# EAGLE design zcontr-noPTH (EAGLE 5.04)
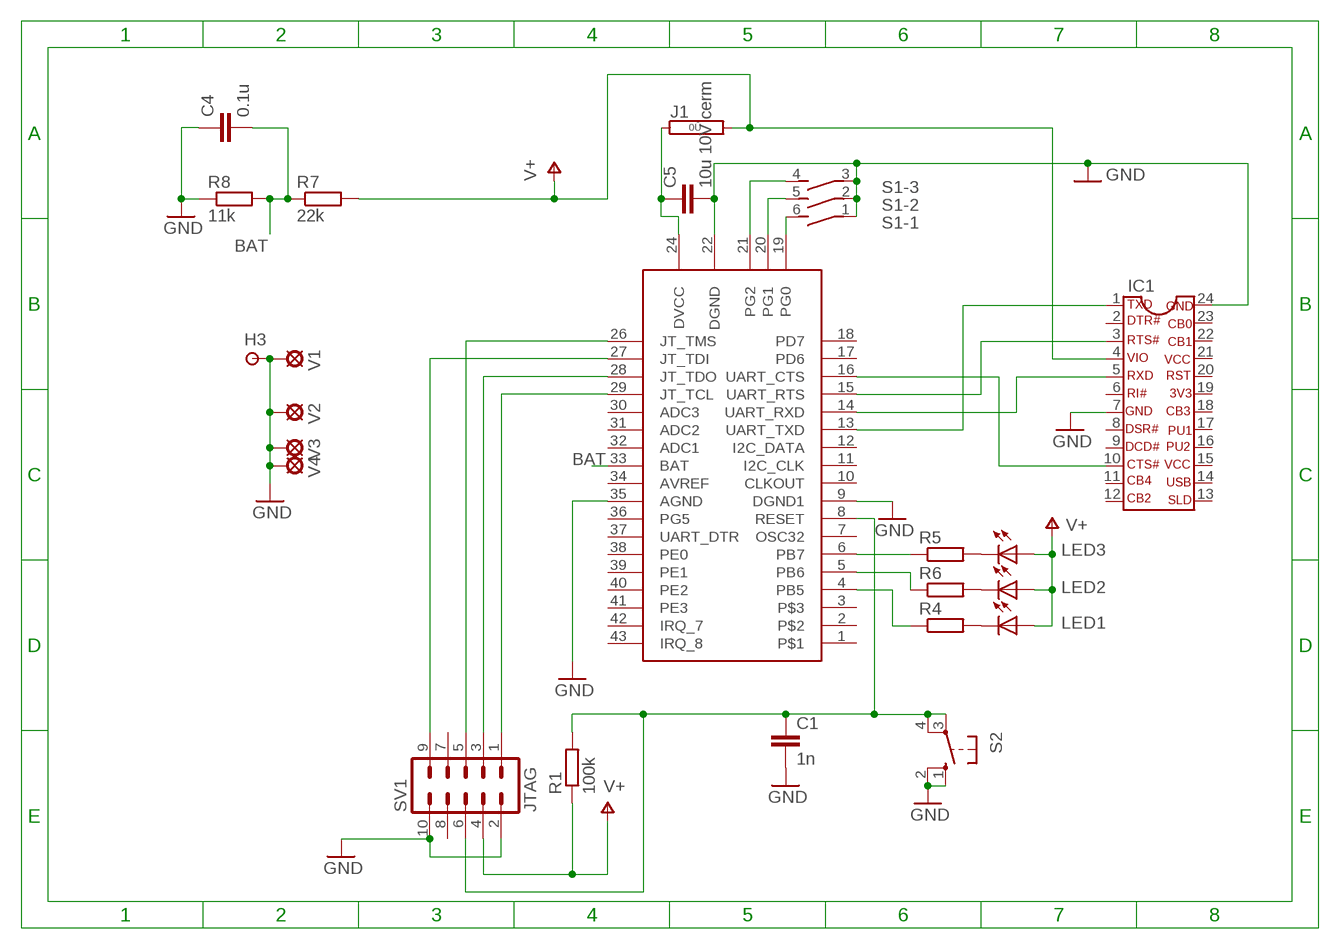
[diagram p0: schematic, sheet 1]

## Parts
C1  1n  C2.5P  [C025-030X050]
C4  0.1u  C5P  [C050-030-075]
C5  10u 10V cerm  CSMT0805  [C0805]
H3  HOLE/SMALL  [1,6/0,8]
IC1  UM232R-6  [DIL24-6]
J1  0R  [0R/10]
LED1  LED-3MM3MM  [HLMP-D105]
LED2  LED-3MM3MM  [HLMP-D105]
LED3  LED-3MM3MM  [HLMP-D105]
R1  100k  R  [0207/10]
R4  470  R  [0207/10]
R5  150  R  [0207/10]
R6  220  R  [0207/10]
R7  22k  R  [0207/10]
R8  11k  R  [0207/10]
S1  DIP-SW-03  [DIP-SW-3]
S2  10-XX  [B3F-10XX]
SV1  JTAG  ML10  [ML10]
U$1  ZDM-A1281-A2N  [ZIGSMD]
V1  HOLE/VIA  [LSP10]
V2  HOLE/VIA  [LSP10]
V3  HOLE/VIA  [LSP10]
V4  HOLE/VIA  [LSP10]

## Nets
BAT: C4.2 R7.1 R8.2 U$1.33(BAT)
GND [supply]: C1.2 C4.1 C5.2 H3.1(P) IC1.7 IC1.24 R8.1 S1.1 S1.2 S1.3 S2.1(S) S2.2(S1) SV1.2 SV1.10 U$1.9(DGND1) U$1.22(DGND) U$1.35(AGND) V1.MP V2.MP V3.MP V4.MP
N$1: S1.6 U$1.19(PG0)
N$2: IC1.10 U$1.16(UART_CTS)
N$3: IC1.3 U$1.15(UART_RTS)
N$4: IC1.5 U$1.14(UART_RXD)
N$5: IC1.1 U$1.13(UART_TXD)
N$6: LED3.K(C) R5.2
N$7: LED2.K(C) R6.2
N$8: LED1.K(C) R4.2
N$9: R5.1 U$1.6(PB7)
N$10: SV1.1 U$1.29(JT_TCL)
N$11: SV1.9 U$1.27(JT_TDI)
N$12: SV1.3 U$1.28(JT_TDO)
N$13: C1.1 R1.2 S2.3(P) S2.4(P1) SV1.6 U$1.8(RESET)
N$14: R6.1 U$1.5(PB6)
N$15: R4.1 U$1.4(PB5)
N$16: S1.5 U$1.20(PG1)
N$17: S1.4 U$1.21(PG2)
N$19: SV1.5 U$1.26(JT_TMS)
N$31 [supply]: C5.1 J1.1 U$1.24(DVCC)
V+: IC1.4 J1.2 LED1.A LED2.A LED3.A R1.1 R7.2 SV1.4
Unconnected: IC1.2 IC1.6 IC1.8 IC1.9 IC1.11 IC1.12 IC1.13 IC1.14 IC1.15 IC1.16 IC1.17 IC1.18 IC1.19 IC1.20 IC1.21 IC1.22 IC1.23 SV1.7 SV1.8 U$1.1 U$1.2 U$1.3 U$1.7(OSC32) U$1.10(CLKOUT) U$1.11(I2C_CLK) U$1.12(I2C_DATA) U$1.17(PD6) U$1.18(PD7) U$1.30(ADC3) U$1.31(ADC2) U$1.32(ADC1) U$1.34(AVREF) U$1.36(PG5) U$1.37(UART_DTR) U$1.38(PE0) U$1.39(PE1) U$1.40(PE2) U$1.41(PE3) U$1.42(IRQ_7) U$1.43(IRQ_8)

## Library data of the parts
C1 C4 C5 = ee2parts:C: Capacitor
H3 = ee2parts:HOLE/SMALL: SMALL THROUGH-HOLE PAD/TESTPOINT
IC1 = ee2parts:UM232R: USB to Serial Module Provides easy USB interface to serial (UART) with power supply
J1 = jumper:0R: Bridge 0R 10mm
LED1-LED3 = ee2parts:LED-3MM: LED
R1 R4-R8 = ee2parts:R: Resistor
S1 = ee2parts:DIP-SW-03: DIL/CODE SWITCH
S2 = switch-omron:10-XX: OMRON SWITCH
SV1 = con-harting-ml:ML10: HARTING
U$1 = 0Zigbit:ZDM-A1281-A2
V1-V4 = ee2parts:HOLE/VIA: FIXED VIA

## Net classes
1 supply: width 0.508 mm

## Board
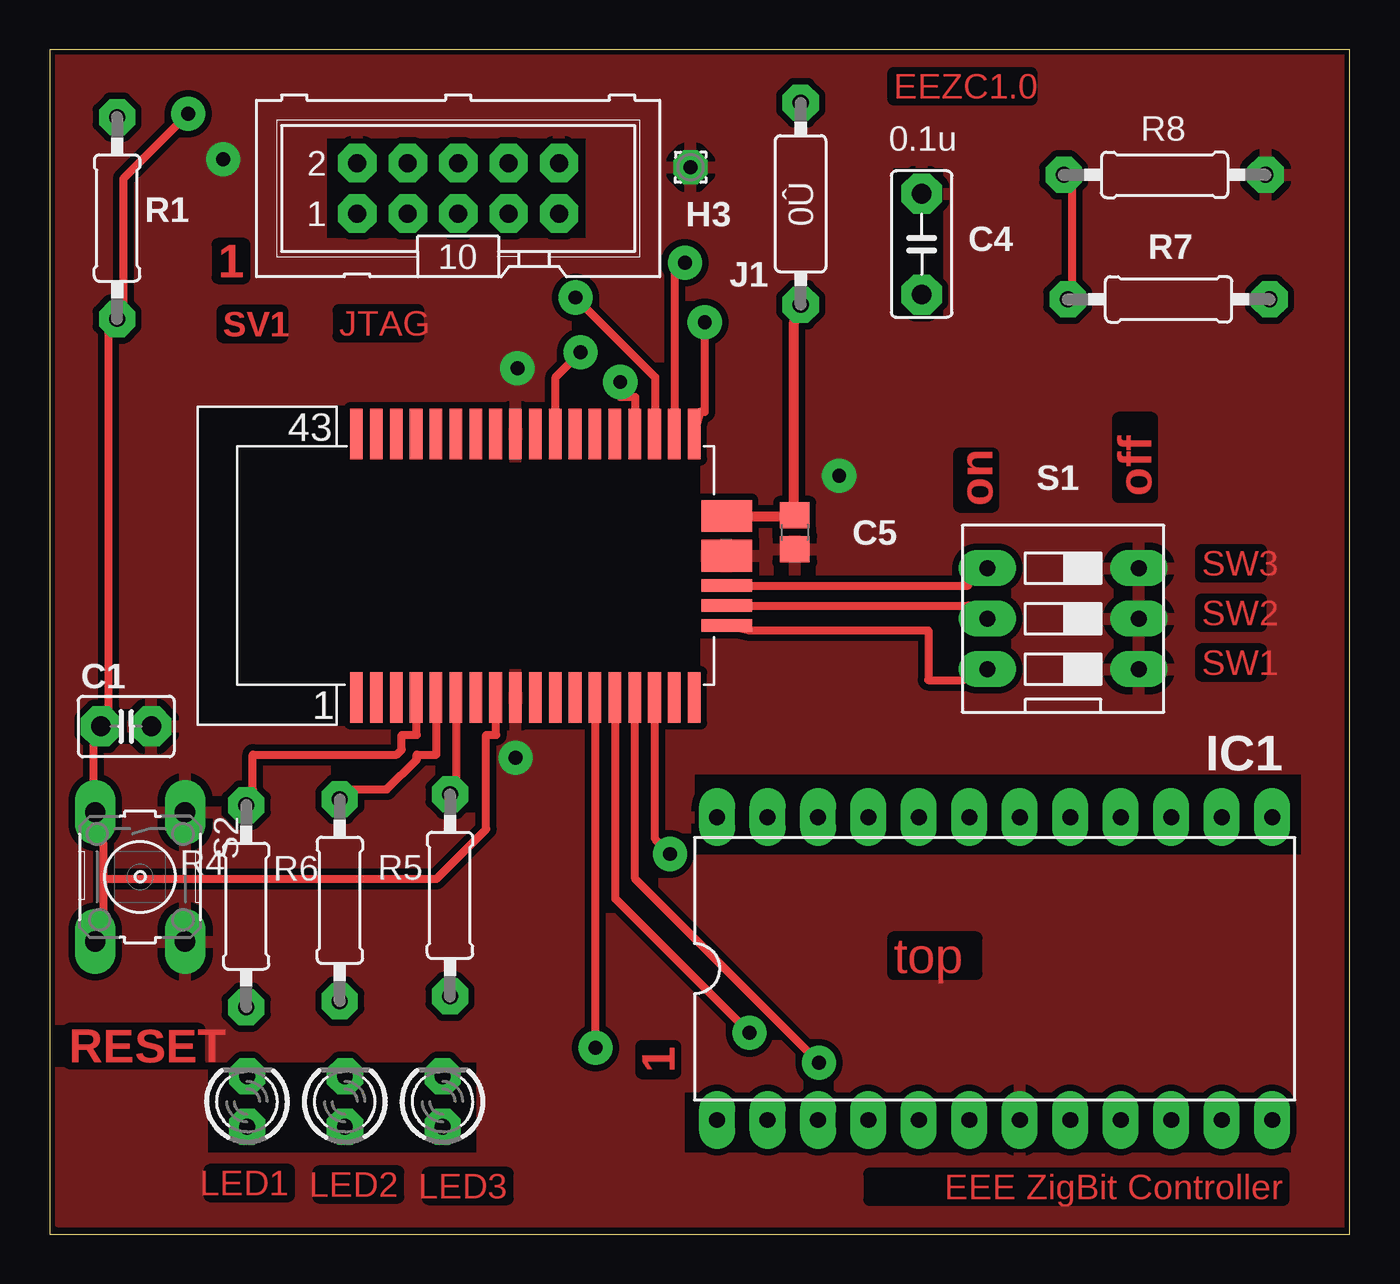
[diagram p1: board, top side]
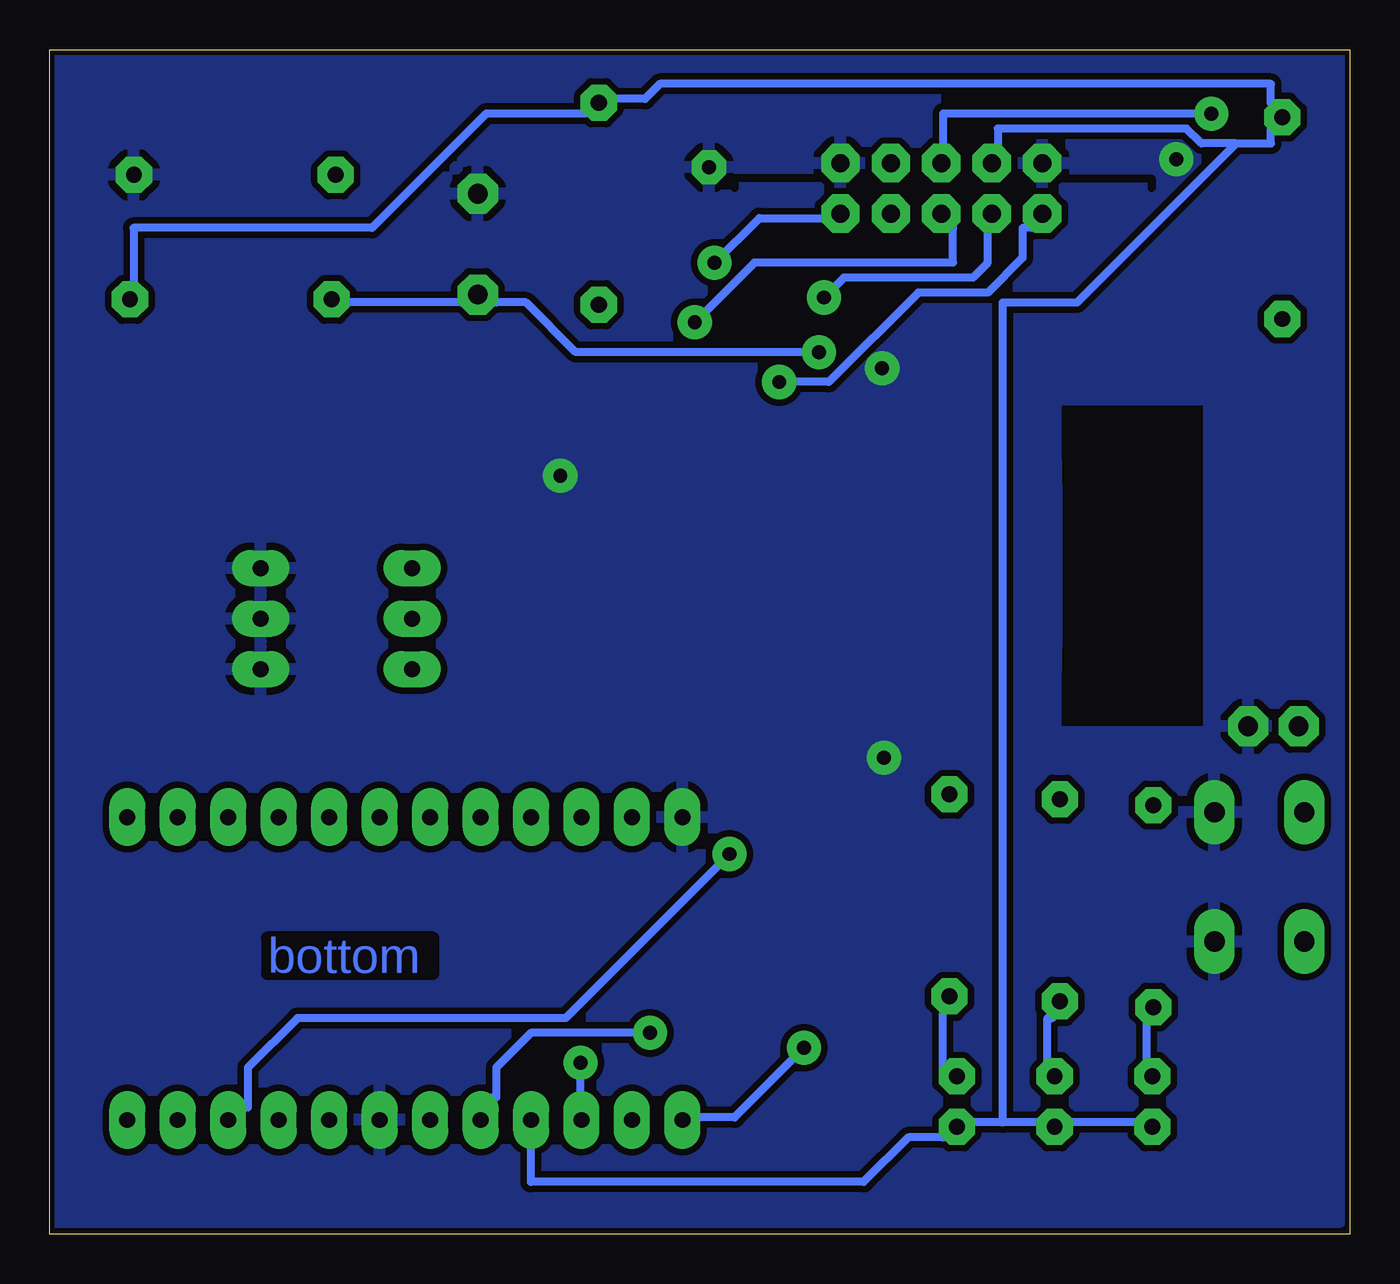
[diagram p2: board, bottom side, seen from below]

Size 65.44 x 59.6 mm. Coordinates in mm from the lower left corner, seen from the top.
Outline: 0,0 65.44,0 65.44,59.6 0,59.6 0,0
Copper layers (1*16): Top 0.035mm / dielectric 1.5mm / Bottom 0.035mm
Design rules "zigbit_rules": minimum track width 16mil, minimum drill 0.7mm, track to track 13mil, track to pad 13mil, pad to pad 13mil, via to via 13mil, smd to smd 0mil, copper to edge 10mil, drill to drill 10mil, minimum pad ring 20mil, minimum via ring 20mil, stop-mask expansion 0mil, vias tented up to drill 0mil, thermal gap 15mil
tRestrict: area 32.5,19.1 to 63,23.1; area 32,4.1 to 62.5,7.1; area 8,4.1 to 21.5,8.6; area 42.5,46.1 to 45,53.6; area 14,50.1 to 27,55.1
bRestrict: 4 lines
vRestrict: area 10,48.1 to 31,57.1

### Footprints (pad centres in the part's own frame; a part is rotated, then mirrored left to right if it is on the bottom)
C025-030X050 = drill 1 octagon: 1 -1.27,0; 2 1.27,0
C050-030-075 = drill 1 octagon: 1 -2.54,0; 2 2.54,0
C0805 = smd 1.3 x 1.5: 1 -0.85,0; 2 0.85,0
1,6/0,8 = drill 0.7 pad 1.6 octagon: 1 0,0
DIL24-6 = drill 0.8 long: 1 -13.97,-7.62; 2 -11.43,-7.62; 3 -8.89,-7.62; 4 -6.35,-7.62; 5 -3.81,-7.62; 6 -1.27,-7.62; 7 1.27,-7.62; 8 3.81,-7.62; 9 6.35,-7.62; 10 8.89,-7.62; 11 11.43,-7.62; 12 13.97,-7.62; 13 13.97,7.62; 14 11.43,7.62; 15 8.89,7.62; 16 6.35,7.62; 17 3.81,7.62; 18 1.27,7.62; 19 -1.27,7.62; 20 -3.81,7.62; 21 -6.35,7.62; 22 -8.89,7.62; 23 -11.43,7.62; 24 -13.97,7.62
0R/10 = drill 0.813 pad 1.6 octagon: 1 -5.08,0; 2 5.08,0
HLMP-D105 = drill 0.8 octagon: A -1.27,0; K 1.27,0
0207/10 = drill 0.8 octagon: 1 -5.08,0; 2 5.08,0
DIP-SW-3 = drill 0.8 long: 1 -2.54,-3.81; 2 0,-3.81; 3 2.54,-3.81; 4 2.54,3.81; 5 0,3.81; 6 -2.54,3.81
B3F-10XX = drill 1.016 long: 1 -3.251,2.261; 2 3.251,2.261; 3 -3.251,-2.261; 4 3.251,-2.261
ML10 = drill 0.914 octagon: 1 -5.08,-1.27; 2 -5.08,1.27; 3 -2.54,-1.27; 4 -2.54,1.27; 5 0,-1.27; 6 0,1.27; 7 2.54,-1.27; 8 2.54,1.27; 9 5.08,-1.27; 10 5.08,1.27
ZIGSMD = smd 0.635 x 2.54: 1 7,6.635; 2 6,6.635; 3 5,6.635; 4 4,6.635; 5 3,6.635; 6 2,6.635; 7 1,6.635; 8 0,6.635; 9 -1,6.635; 10 -2,6.635; 11 -3,6.635; 12 -4,6.635; 13 -5,6.635; 14 -6,6.635; 15 -7,6.635; 16 -8,6.635; 17 -9,6.635; 18 -10,6.635; 26 -10,-6.635; 27 -9,-6.635; 28 -8,-6.635; 29 -7,-6.635; 30 -6,-6.635; 31 -5,-6.635; 32 -4,-6.635; 33 -3,-6.635; 34 -2,-6.635; 35 -1,-6.635; 36 0,-6.635; 37 1,-6.635; 38 2,-6.635; 39 3,-6.635; 40 4,-6.635; 41 5,-6.635; 42 6,-6.635; 43 7,-6.635 | smd 2.54 x 0.635: 19 -11.635,3; 20 -11.635,2; 21 -11.635,1 | smd 2.54 x 1.6: 22 -11.635,-0.5; 24 -11.635,-2.5
LSP10 = drill 0.7 pad 1.016 round: MP 0,0

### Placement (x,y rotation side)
C1  3.85,25.55 0 top
C4  43.89,49.82 270 top
C5  37.5,35.32 270 top
H3  32.26,53.68 0 top
IC1  47.56,13.37 0 top
J1  37.8,51.85 90 top
LED1  9.94,6.67 90 top
LED2  14.86,6.67 90 top
LED3  19.78,6.67 90 top
R1  3.39,51.13 270 top
R4  9.89,16.51 270 top
R5  20.14,17.05 270 top
R6  14.6,16.8 270 top
R7  56.32,47.04 0 top
R8  56.12,53.3 180 top
S1  51.01,30.97 90 top
S2  4.55,17.98 270 top
SV1  20.56,52.62 0 top
U$1  22.44,33.64 180 top
V1  8.74,54.09 0 top
V2  23.54,43.58 0 top
V3  23.44,23.97 0 top
V4  39.74,38.16 0 top

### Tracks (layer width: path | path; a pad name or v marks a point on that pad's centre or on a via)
BAT  (via drill 0.7)
  Top 0.406: R7.1 51.47,47.88 51.47,52.63 R8.2 | v26.72,44.38 25.47,43.13 25.47,41.38 U$1.33
  Bottom 0.406: v26.72,44.38 38.97,44.38 41.47,46.88 42.97,46.88 C4.2 44.72,46.88 50.47,46.88 R7.1
GND
  pour Bottom: 0.47,59.25 65.28,59.25 65.28,0.63 0.47,0.63
  pour Top: 0.47,59.25 65.28,59.25 65.28,0.63 0.47,0.63
N$1
  Top 0.406: U$1.19 35.22,30.38 44.22,30.38 44.22,27.88 45.97,27.88 S1.6
N$2  (via drill 0.7)
  Top 0.406: v31.22,19.13 30.47,19.88 30.47,25.88 U$1.16
  Bottom 0.406: v31.22,19.13 39.47,10.88 52.97,10.88 55.47,8.38 55.47,6.38 55.72,6.38 IC1.10
N$3  (via drill 0.7)
  Top 0.406: v38.72,8.63 29.47,17.88 29.47,25.88 U$1.15
  Bottom 0.406: v38.72,8.63 38.72,7.13 IC1.3
N$4  (via drill 0.7)
  Top 0.406: v35.22,10.13 28.47,16.88 28.47,25.88 U$1.14
  Bottom 0.406: v35.22,10.13 41.22,10.13 42.97,8.38 42.97,6.88 43.22,6.88 IC1.5
N$5  (via drill 0.7)
  Top 0.406: v27.47,9.38 27.47,25.88 U$1.13
  Bottom 0.406: v27.47,9.38 30.97,5.88 32.72,5.88 IC1.1
N$6
  Bottom 0.406: LED3.K 20.47,8.38 20.47,11.13 R5.2
N$7
  Bottom 0.406: LED2.K 15.22,8.63 15.22,10.88 14.97,10.88 R6.2
N$8
  Bottom 0.406: LED1.K 10.22,8.63 10.22,10.63 R4.2
N$9
  Top 0.406: U$1.6 20.47,25.88 20.47,22.88 R5.1
N$10  (via drill 0.7)
  Top 0.406: v28.72,42.88 28.72,42.13 29.47,42.13 29.47,41.38 U$1.29
  Bottom 0.406: v28.72,42.88 26.22,42.88 21.72,47.38 18.22,47.38 16.47,49.13 16.47,50.63 15.97,50.63 SV1.1
N$11  (via drill 0.7)
  Top 0.406: v31.97,48.88 31.47,48.38 31.47,41.38 U$1.27
  Bottom 0.406: v31.97,48.88 29.72,51.13 26.47,51.13 SV1.9
N$12  (via drill 0.7)
  Top 0.406: v26.47,47.13 30.47,43.13 30.47,41.38 U$1.28
  Bottom 0.406: v26.47,47.13 25.47,48.13 18.97,48.13 18.22,48.88 18.22,50.63 SV1.3
N$13  (via drill 0.7)
  Top 0.406: 2.72,17.88 19.47,17.88 21.97,20.38 21.97,25.13 22.47,25.13 22.47,25.88 U$1.8 | 2.72,17.88 2.72,19.63 S2.3 2.22,22.63 2.22,24.63 C1.1 2.97,26.38 2.97,45.38 R1.2 3.72,46.88 3.72,53.13 v6.97,56.38 | 2.72,17.88 2.72,16.13 S2.4
  Bottom 0.406: v6.97,56.38 20.47,56.38 20.47,54.63 SV1.6
N$14
  Top 0.406: U$1.5 19.47,25.88 19.47,24.13 18.47,24.13 18.47,23.88 16.97,22.38 15.22,22.38 R6.1
N$15
  Top 0.406: U$1.4 18.47,25.88 18.47,25.13 17.72,25.13 17.72,24.38 17.47,24.13 10.22,24.13 10.22,22.38 R4.1
N$16
  Top 0.406: U$1.20 35.22,31.63 46.22,31.63 S1.5
N$17
  Top 0.406: U$1.21 35.22,32.63 46.22,32.63 46.22,32.88 S1.4
N$19  (via drill 0.7)
  Top 0.406: v32.97,45.88 32.97,41.38 32.72,41.38 U$1.26
  Bottom 0.406: v32.97,45.88 29.97,48.88 19.97,48.88 19.97,50.63 SV1.5
N$31
  Top 0.508: U$1.24 35.22,36.13 36.97,36.13 C5.1 37.47,36.63 37.47,45.88 J1.1
V+
  Bottom 0.406: LED1.A 10.72,5.63 13.97,5.63 LED2.A 15.72,5.63 17.47,5.63 | 17.47,5.63 18.97,5.63 LED3.A 20.47,4.88 22.22,4.88 24.47,2.63 41.22,2.63 41.22,4.38 IC1.4 | 5.72,54.88 7.47,54.88 8.22,55.63 17.72,55.63 17.72,54.63 SV1.4 | 5.72,54.88 3.97,54.88 3.97,55.63 R1.1 3.97,56.88 3.97,57.88 34.72,57.88 35.47,57.13 36.97,57.13 J1.2 38.47,56.38 43.47,56.38 49.22,50.63 61.22,50.63 61.22,47.88 R7.2 | 17.47,5.63 17.47,46.88 13.72,46.88 5.72,54.88

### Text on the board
Top: EEZC1.0 | 1 | on | off | SW3 | SW2 | SW1 | top | RESET | 1 | EEE ZigBit Controller
Bottom: bottom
